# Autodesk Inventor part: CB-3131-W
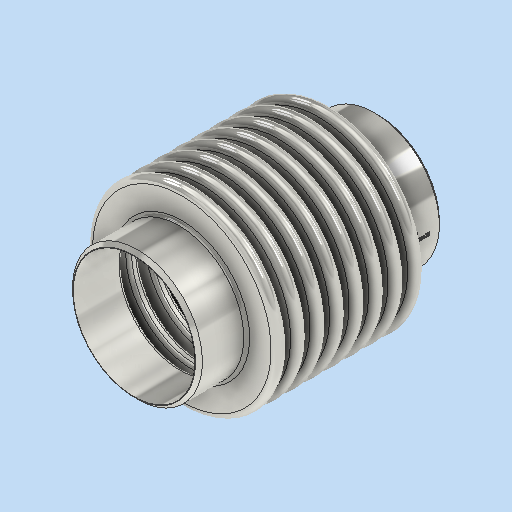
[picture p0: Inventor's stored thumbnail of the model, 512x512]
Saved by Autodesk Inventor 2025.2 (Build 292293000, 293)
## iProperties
Company: DN.RU
Created: 2026-04
Part Number: CB-3131-W
Material: Типовые
Document SubType Name: Modeling
Designer: DN.RU
Density: 5.56225 g/cm^3
Appearance: По умолчанию
Description: D140-02125
Mass: 2600 g
Surface Area: 6882.51 cm^2
Volume: 467.437 cm^3
Author: DN.RU
Title: Компенсатор сильфонный осевой DN.ru Ду125 Ру16
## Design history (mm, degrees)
sketch "Эскиз1"
  geometry: L1 (0, 0)-(0, -125); L2 (66.5, -125)-(66.5, 0); L3 (66.5, 0)-(0, 0); L4 (66.5, 0)-(66.5, -10); L5 (41.5, -10)-(91.5, -10); L6 (41.5, -16)-(91.5, -16); L7 (91.5, -4)-(41.5, -4); L8 (91.5, -15)-(41.5, -15); L9 (41.5, -5)-(91.5, -5); L10 (91.5, -24)-(41.5, -24); L11 (41.5, -25)-(91.5, -25); L12 (41.5, -30)-(91.5, -30); L13 (41.5, -36)-(91.5, -36); L14 (91.5, -35)-(41.5, -35); L15 (91.5, -44)-(41.5, -44); L16 (41.5, -45)-(91.5, -45); L17 (41.5, -50)-(91.5, -50); L18 (41.5, -56)-(91.5, -56); L19 (91.5, -55)-(41.5, -55); L20 (91.5, -64)-(41.5, -64); L21 (41.5, -65)-(91.5, -65); L22 (41.5, -70)-(91.5, -70); L23 (41.5, -76)-(91.5, -76); L24 (91.5, -75)-(41.5, -75); L25 (0, -125)-(66.5, -125); L26 (66.5, -125)-(62.5, -125); L27 (66.5, -64)-(65.5, -64); L28 (62.5, -125)-(62.5, -75); L29 (66.5, -65)-(65.5, -65); L30 (65.5, -65)-(65.5, -55); L31 (66.5, -45)-(65.5, -45); L32 (65.5, -45)-(65.5, -35); L33 (66.5, -25)-(65.5, -25); L34 (65.5, -25)-(65.5, -15); L35 (66.5, -5)-(65.5, -5); L36 (65.5, -5)-(65.5, 0); A1 r 6 centre (41.5, -10) between (41.5, -4) and (41.5, -16); A2 r 6 centre (91.5, -10) between (91.5, -16) and (91.5, -4); A3 r 5 centre (41.5, -10) between (41.5, -5) and (41.5, -15); A4 r 5 centre (91.5, -10) between (91.5, -15) and (91.5, -5); A5 r 5 centre (41.5, -30) between (41.5, -25) and (41.5, -35); A6 r 6 centre (41.5, -30) between (41.5, -24) and (41.5, -36); A7 r 5 centre (91.5, -30) between (91.5, -35) and (91.5, -25); A8 r 6 centre (91.5, -30) between (91.5, -36) and (91.5, -24); A9 r 5 centre (41.5, -50) between (41.5, -45) and (41.5, -55); A10 r 6 centre (41.5, -50) between (41.5, -44) and (41.5, -56); A11 r 5 centre (91.5, -50) between (91.5, -55) and (91.5, -45); A12 r 6 centre (91.5, -50) between (91.5, -56) and (91.5, -44); A13 r 5 centre (41.5, -70) between (41.5, -65) and (41.5, -75); A14 r 6 centre (41.5, -70) between (41.5, -64) and (41.5, -76); A15 r 5 centre (91.5, -70) between (91.5, -75) and (91.5, -65); A16 r 6 centre (91.5, -70) between (91.5, -76) and (91.5, -64); 18 further points
  constraints: 80 end point, 32 point on circle, 16 centre point, 15 point on line, 6 midpoint, 5 perpendicular, 4 tangent, 3 parallel, 2 vertical, 1 horizontal, 69 other
  dimensions: "d0" = 125 distance of L1.start L1.end; "d1" = 66.5 distance of L2.start L1.end; "d3" = 10 distance of L2.end L4.end; "d4" = 25 distance of L4.end L5.end; "d5" = 12 diameter of A2; "d6" = 1 distance between parallel lines of L6 L8; "d9" = 20 distance of L4.end point (66.5, -30); "d14" = 4 distance of L2.start L26.end; "d15" = 1 distance of L27.start L27.end; "d16" = 1 distance of L29.start L29.end; "d17" = 1 distance of L31.start L31.end; "d18" = 1 distance of L33.start L33.end; "d19" = 1 distance of L35.start L35.end
revolve "Вращение1" sketch "Эскиз1" stored, may be unused: angle "d20" = 360 deg
mirror "Зеркальное отражение1"
chamfer "Фаска1" distance "d21" = 3.5; stored, may be unused: second distance "d22" = 2, angle "d23" = 45 deg
fillet "Сопряжение1" dims "d24" = 3
node "РабПлоскость1"
sketch "Эскиз2"
  geometry: L1 (4.893, 15.322)-(4.893, -12.74); L2 (4.893, -12.74)-(-3.237, -12.74); L3 (-3.237, -12.74)-(-3.237, 15.322); L4 (-3.237, 15.322)-(4.893, 15.322); 1 further point
  constraints: 2 other
feature "Рельеф1" sketch "Эскиз2" dims "d25" = 0.1, "d26" = 0
node "Твердое тело1"
node "Эскиз — прямоугольный массив1" dims "d9" = 20, "d12" = 10
